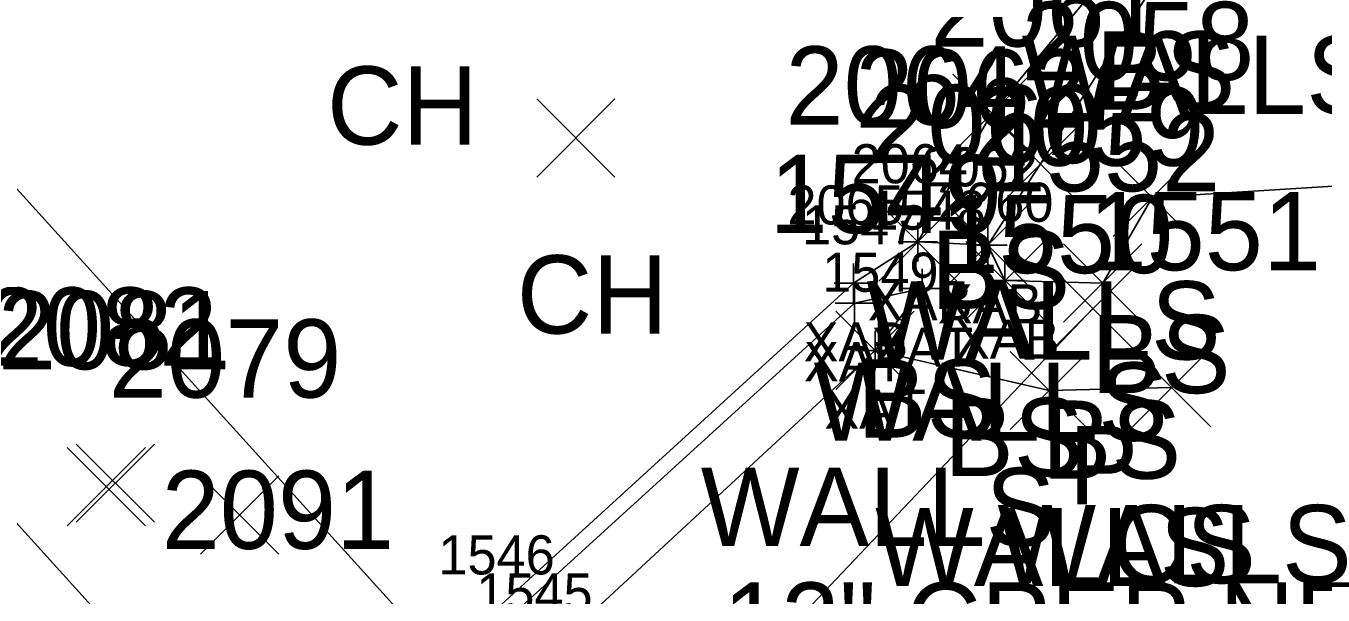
# Model space of a CAD drawing. Extents: x 1499292 to 1501024, y 534584 to 538043.
# Drawn here: x 1499836.82 to 1499870.01, y 537690.04 to 537704.58 of the extents above; entities that cross this region are included whole.
import ezdxf

# ---------------------------------------------------------------- set-up
doc = ezdxf.new("R2010")
doc.units = 0
for name, color, linetype in [('B_A', 7, 'Continuous'), ('B_I', 7, 'Continuous'), ('B_TIC', 7, 'Continuous'), ('BELB', 7, 'Continuous'), ('BSUBM', 7, 'Continuous'), ('D_A', 7, 'Continuous'), ('D_C', 7, 'Continuous'), ('D_I', 7, 'Continuous'), ('D_TIC', 7, 'Continuous'), ('DCP', 7, 'Continuous'), ('L_A', 7, 'Continuous'), ('L_I', 7, 'Continuous'), ('L_TIC', 7, 'Continuous'), ('LELB', 7, 'Continuous'), ('LWS', 7, 'Continuous')]:
    doc.layers.add(name, color=color, linetype=linetype)

msp = doc.modelspace()

# ---------------------------------------------------------------- linework, layer by layer
at = {"layer": 'B_TIC'}
for p, q in [((1499859.646, 537699.06), (1499859.722, 537699.06)), ((1499861.435, 537698.979), (1499861.51, 537698.979)), ((1499858.002, 537698.007), (1499858.077, 537698.007)), ((1499861.875, 537698.076), (1499861.951, 537698.076)), ((1499859.754, 537697.874), (1499859.83, 537697.874)), ((1499858.028, 537697.5), (1499858.103, 537697.5)), ((1499858.55, 537696.288), (1499858.626, 537696.288)), ((1499858.55, 537696.288), (1499858.626, 537696.288))]:
    msp.add_line(p, q, dxfattribs=at)
for points in [[(1499859.643, 537698.56), (1499859.643, 537699.56)], [(1499861.431, 537698.479), (1499861.431, 537699.479)], [(1499859.143, 537699.06), (1499860.143, 537699.06)], [(1499860.931, 537698.979), (1499861.931, 537698.979)], [(1499857.998, 537697.507), (1499857.998, 537698.507)], [(1499859.751, 537697.374), (1499859.751, 537698.374)], [(1499861.872, 537697.576), (1499861.872, 537698.576)], [(1499857.498, 537698.007), (1499858.498, 537698.007)], [(1499858.024, 537697), (1499858.024, 537698)], [(1499861.372, 537698.076), (1499862.372, 537698.076)], [(1499859.251, 537697.874), (1499860.251, 537697.874)], [(1499857.524, 537697.5), (1499858.524, 537697.5)], [(1499858.547, 537695.788), (1499858.547, 537696.788)], [(1499858.547, 537695.788), (1499858.547, 537696.788)], [(1499858.047, 537696.288), (1499859.047, 537696.288)], [(1499858.047, 537696.288), (1499859.047, 537696.288)]]:
    msp.add_lwpolyline(points, dxfattribs=at)
at = {"layer": 'BELB'}
for points in [[(1499818.151, 537712.232), (1499822.399, 537716.076), (1499857.204, 537677.674), (1499852.942, 537673.812)], [(1499818.151, 537712.232), (1499852.942, 537673.812)]]:
    msp.add_lwpolyline(points, dxfattribs=at)
at = {"layer": 'BSUBM'}
for points in [[(1499861.872, 537698.076), (1499861.431, 537698.979), (1499859.643, 537699.06), (1499857.998, 537698.007), (1499846.06, 537687.129), (1499832.903, 537675.175), (1499827.097, 537669.958), (1499820.539, 537664.322), (1499814.391, 537657.152), (1499810.191, 537652.285)], [(1499840.44, 537679.978), (1499839.802, 537680.82), (1499848.749, 537689.062), (1499858.024, 537697.5), (1499859.751, 537697.874), (1499858.547, 537696.288)], [(1499840.44, 537679.978), (1499849.692, 537688.093), (1499858.547, 537696.288)]]:
    msp.add_lwpolyline(points, dxfattribs=at)
at = {"layer": 'D_TIC'}
for points in [[(1499863.123, 537696.357), (1499865.123, 537698.357)], [(1499865.123, 537696.357), (1499863.123, 537698.357)]]:
    msp.add_lwpolyline(points, dxfattribs=at)
at = {"layer": 'DCP'}
msp.add_lwpolyline([(1499864.123, 537697.357), (1499846.92, 537679.237)], dxfattribs=at)
at = {"layer": 'L_TIC'}
for points in [[(1499860.535, 537701.351), (1499862.535, 537703.351)], [(1499862.535, 537701.351), (1499860.535, 537703.351)], [(1499849.893, 537700.72), (1499851.893, 537702.72)], [(1499851.893, 537700.72), (1499849.893, 537702.72)], [(1499861.781, 537700.056), (1499863.781, 537702.056)], [(1499863.781, 537700.056), (1499861.781, 537702.056)], [(1499864.638, 537699.196), (1499866.638, 537701.196)], [(1499866.638, 537699.196), (1499864.638, 537701.196)], [(1499858.643, 537698.06), (1499860.643, 537700.06)], [(1499860.643, 537698.06), (1499858.643, 537700.06)], [(1499860.431, 537697.979), (1499862.431, 537699.979)], [(1499862.431, 537697.979), (1499860.431, 537699.979)], [(1499860.872, 537697.076), (1499862.872, 537699.076)], [(1499862.872, 537697.076), (1499860.872, 537699.076)], [(1499863.372, 537697.009), (1499865.372, 537699.009)], [(1499865.372, 537697.009), (1499863.372, 537699.009)], [(1499857.547, 537695.288), (1499859.547, 537697.288)], [(1499859.547, 537695.288), (1499857.547, 537697.288)], [(1499865.136, 537694.338), (1499867.136, 537696.338)], [(1499867.136, 537694.338), (1499865.136, 537696.338)], [(1499865.136, 537694.338), (1499867.136, 537696.338)], [(1499867.136, 537694.338), (1499865.136, 537696.338)], [(1499862.005, 537694.264), (1499864.005, 537696.264)], [(1499864.005, 537694.264), (1499862.005, 537696.264)], [(1499837.877, 537691.806), (1499839.877, 537693.806)], [(1499839.877, 537691.806), (1499837.877, 537693.806)], [(1499838.108, 537691.896), (1499840.108, 537693.896)], [(1499840.108, 537691.896), (1499838.108, 537693.896)], [(1499841.289, 537691.083), (1499843.289, 537693.083)], [(1499843.289, 537691.083), (1499841.289, 537693.083)]]:
    msp.add_lwpolyline(points, dxfattribs=at)
at = {"layer": 'LELB'}
for points in [[(1499958.724, 537820.121), (1499949.099, 537803.701), (1499937.207, 537786.88), (1499926.5, 537779.141), (1499915.434, 537766.609), (1499901.39, 537746.714), (1499889.513, 537737.266), (1499877.766, 537721.1), (1499874.077, 537712.657), (1499871.122, 537712.1), (1499865.758, 537707.441), (1499861.535, 537702.351), (1499859.643, 537699.06)], [(1499880.51, 537699.897), (1499873.397, 537700.686), (1499865.638, 537700.196), (1499864.372, 537698.009), (1499861.872, 537698.076)]]:
    msp.add_lwpolyline(points, dxfattribs=at)
at = {"layer": 'LWS'}
for points in [[(1499876.181, 537705.711), (1499873.264, 537711.082), (1499866.755, 537707.335), (1499862.781, 537701.056), (1499861.431, 537698.979)], [(1499858.547, 537696.288), (1499863.005, 537695.264), (1499866.136, 537695.338)]]:
    msp.add_lwpolyline(points, dxfattribs=at)

# ---------------------------------------------------------------- texts
at = {"layer": 'B_A'}
for s, p in [('XAB', (1499858.363, 537697.06)), ('XAB', (1499860.152, 537696.979)), ('XAB', (1499856.719, 537696.007)), ('XAB', (1499860.592, 537696.076)), ('XAT', (1499858.456, 537695.874)), ('XAT', (1499856.729, 537695.5)), ('XAT', (1499857.251, 537694.288)), ('XAT', (1499857.251, 537694.288))]:
    msp.add_text(s, height=1, dxfattribs=at).set_placement(p)
at = {"layer": 'B_I'}
for s, p in [('2064', (1499857.95, 537700.56)), ('2062', (1499859.738, 537700.479)), ('2065', (1499856.305, 537699.507)), ('1548', (1499858.404, 537699.374)), ('2060', (1499860.136, 537699.576)), ('1547', (1499856.678, 537699)), ('1549', (1499857.196, 537697.788)), ('1549', (1499857.196, 537697.788)), ('1546', (1499847.375, 537690.562)), ('1545', (1499848.345, 537689.593))]:
    msp.add_text(s, height=1, dxfattribs=at).set_placement(p)
at = {"layer": 'D_A'}
msp.add_text('P', height=2, dxfattribs=at).set_placement((1499863.501, 537692.357))
at = {"layer": 'D_C'}
msp.add_text('12" CPEP NEW', height=2, dxfattribs=at).set_placement((1499854.658, 537688.357))
at = {"layer": 'D_I'}
msp.add_text('1552', height=2, dxfattribs=at).set_placement((1499861.43, 537700.357))
at = {"layer": 'L_A'}
for s, p in [('WALLS', (1499862.299, 537702.335)), ('BS', (1499864.199, 537702.441)), ('CH', (1499844.524, 537701.547)), ('BS', (1499859.976, 537697.351)), ('CH', (1499849.381, 537696.72)), ('WALLS', (1499858.325, 537696.056)), ('BS', (1499864.079, 537695.196)), ('WALLS', (1499856.975, 537693.979)), ('BS', (1499858.084, 537694.06)), ('BS', (1499860.313, 537693.076)), ('BS', (1499862.813, 537693.009)), ('WALLS', (1499854.09, 537691.288)), ('WALLS', (1499861.679, 537690.338)), ('CS', (1499864.577, 537690.338)), ('WALLS', (1499858.548, 537690.264))]:
    msp.add_text(s, height=2, dxfattribs=at).set_placement(p)
at = {"layer": 'L_I'}
for s, p in [('2061', (1499859.962, 537704.056)), ('2058', (1499862.299, 537703.196)), ('2064', (1499856.257, 537702.06)), ('2062', (1499858.046, 537701.979)), ('2060', (1499858.399, 537701.076)), ('2059', (1499861.026, 537701.009)), ('1549', (1499855.846, 537699.288)), ('1550', (1499860.226, 537698.264)), ('1551', (1499864.01, 537698.338)), ('1551', (1499864.01, 537698.338)), ('2082', (1499835.769, 537695.896)), ('2081', (1499836.105, 537695.806)), ('2079', (1499838.943, 537695.083)), ('2091', (1499840.294, 537691.216))]:
    msp.add_text(s, height=2, dxfattribs=at).set_placement(p)

doc.saveas('drawing.dxf')
